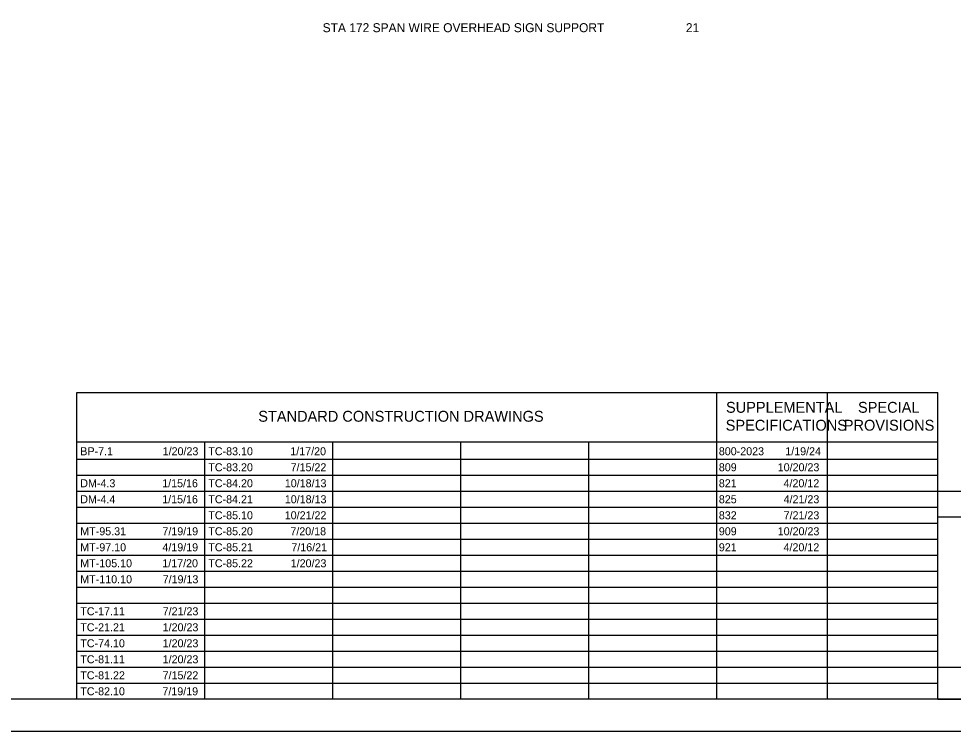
# Model space of a CAD drawing. Extents: x 25.6 to 80.6, y 0.2 to 24.5.
# Drawn here: x 44.76 to 59.36, y 0.23 to 11.36 of the extents above; entities that cross this region are included whole.
import ezdxf

# ---------------------------------------------------------------- set-up
doc = ezdxf.new("R2010")
doc.units = 0
for name, color, linetype in [('Default', 7, 'Continuous'), ('SH_Border', 7, 'Continuous'), ('SH_Cut_Line', 7, 'Continuous'), ('SH_Data', 7, 'Continuous'), ('SH_Text', 7, 'Continuous')]:
    doc.layers.add(name, color=color, linetype=linetype)

msp = doc.modelspace()

# ---------------------------------------------------------------- linework, layer by layer
at = {"layer": 'SH_Border'}
msp.add_lwpolyline([(37.013, 21.73), (69.013, 21.73), (69.013, 0.73), (37.013, 0.73)], close=True, dxfattribs=at)
at = {"layer": 'SH_Cut_Line'}
msp.add_lwpolyline([(35.513, 0.23), (69.513, 0.23), (69.513, 22.23), (35.513, 22.23)], close=True, dxfattribs=at)
at = {"layer": 'SH_Data'}
for p, q in [((45.663, 5.522), (59.113, 5.522)), ((45.663, 0.73), (45.663, 5.522)), ((55.663, 0.73), (55.663, 5.522)), ((57.388, 0.73), (57.388, 5.522)), ((59.113, 0.73), (59.113, 5.522)), ((45.663, 4.751), (59.113, 4.751)), ((47.663, 0.73), (47.663, 4.751)), ((49.663, 0.73), (49.663, 4.751)), ((51.663, 0.73), (51.663, 4.751)), ((53.663, 0.73), (53.663, 4.751)), ((45.663, 4.48), (59.113, 4.48)), ((45.663, 4.23), (59.113, 4.23)), ((45.663, 3.98), (59.113, 3.98)), ((59.113, 0.73), (59.113, 3.98)), ((59.113, 3.98), (61.913, 3.98)), ((45.663, 3.73), (59.113, 3.73)), ((59.113, 3.58), (61.913, 3.58)), ((45.663, 3.48), (59.113, 3.48)), ((45.663, 3.23), (59.113, 3.23)), ((45.663, 2.98), (59.113, 2.98)), ((45.663, 2.73), (59.113, 2.73)), ((45.663, 2.48), (59.113, 2.48)), ((45.663, 2.23), (59.113, 2.23)), ((45.663, 1.98), (59.113, 1.98)), ((45.663, 1.73), (59.113, 1.73)), ((45.663, 1.48), (59.113, 1.48)), ((45.663, 1.23), (59.113, 1.23)), ((45.663, 0.98), (59.113, 0.98)), ((59.113, 0.73), (61.913, 0.73))]:
    msp.add_line(p, q, dxfattribs=at)
msp.add_lwpolyline([(59.113, 0.73), (59.113, 1.23), (61.913, 1.23), (61.913, 0.73)], close=True, dxfattribs=at)

# ---------------------------------------------------------------- texts
at = {"layer": 'Default'}
for s, p in [('1/20/23', (47.005, 4.543)), ('1/17/20', (48.999, 4.543)), ('BP-7.1', (45.718, 4.543)), ('TC-83.10', (47.718, 4.543)), ('809', (55.693, 4.293)), ('10/20/23', (56.613, 4.293)), ('DM-4.3', (45.718, 4.043)), ('1/15/16', (46.998, 4.043)), ('821', (55.693, 4.043)), ('4/20/12', (56.704, 4.043)), ('DM-4.4', (45.718, 3.793)), ('1/15/16', (46.998, 3.793)), ('825', (55.693, 3.793)), ('4/21/23', (56.705, 3.793)), ('TC-85.10', (47.718, 3.543)), ('10/21/22', (48.912, 3.543)), ('832', (55.693, 3.543)), ('7/21/23', (56.705, 3.543)), ('MT-95.31', (45.718, 3.293)), ('7/19/19', (47.001, 3.293)), ('909', (55.693, 3.293)), ('10/20/23', (56.613, 3.293)), ('MT-97.10', (45.718, 3.043)), ('4/19/19', (47.001, 3.043)), ('921', (55.693, 3.043)), ('4/20/12', (56.704, 3.043)), ('1/17/20', (46.999, 2.793)), ('MT-105.10', (45.718, 2.793)), ('MT-110.10', (45.718, 2.543)), ('7/19/13', (47.005, 2.543)), ('TC-17.11', (45.718, 2.043)), ('7/21/23', (47.005, 2.043)), ('TC-21.21', (45.718, 1.793)), ('1/20/23', (47.005, 1.793)), ('TC-74.10', (45.718, 1.543)), ('1/20/23', (47.005, 1.543))]:
    msp.add_text(s, height=0.125, dxfattribs=at).set_placement(p)
at = {"layer": 'SH_Text'}
for s, height, p in [('STA 172 SPAN WIRE OVERHEAD SIGN SUPPORT', 0.14, (49.504, 11.153)), ('21', 0.14, (55.178, 11.153)), ('SUPPLEMENTAL', 0.17, (55.805, 5.207)), ('SPECIAL', 0.17, (57.867, 5.207)), ('STANDARD CONSTRUCTION DRAWINGS', 0.17, (48.498, 5.067)), ('SPECIFICATIONS', 0.17, (55.8, 4.927)), ('PROVISIONS', 0.17, (57.645, 4.927)), ('1/19/24', 0.125, (56.731, 4.543)), ('800-2023', 0.125, (55.693, 4.543)), ('TC-83.20', 0.125, (47.718, 4.293)), ('7/15/22', 0.125, (49.004, 4.293)), ('TC-84.20', 0.125, (47.718, 4.043)), ('10/18/13', 0.125, (48.913, 4.043)), ('TC-84.21', 0.125, (47.718, 3.793)), ('10/18/13', 0.125, (48.913, 3.793)), ('TC-85.20', 0.125, (47.718, 3.293)), ('7/20/18', 0.125, (49, 3.293)), ('TC-85.21', 0.125, (47.718, 3.043)), ('7/16/21', 0.125, (49.015, 3.043)), ('1/20/23', 0.125, (49.005, 2.793)), ('TC-85.22', 0.125, (47.718, 2.793)), ('TC-81.11', 0.125, (45.718, 1.293)), ('1/20/23', 0.125, (47.005, 1.293)), ('TC-81.22', 0.125, (45.718, 1.043)), ('7/15/22', 0.125, (47.004, 1.043)), ('TC-82.10', 0.125, (45.718, 0.793)), ('7/19/19', 0.125, (47.001, 0.793))]:
    msp.add_text(s, height=height, dxfattribs=at).set_placement(p)

doc.saveas('drawing.dxf')
